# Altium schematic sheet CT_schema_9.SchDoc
size 281 x 153 mm
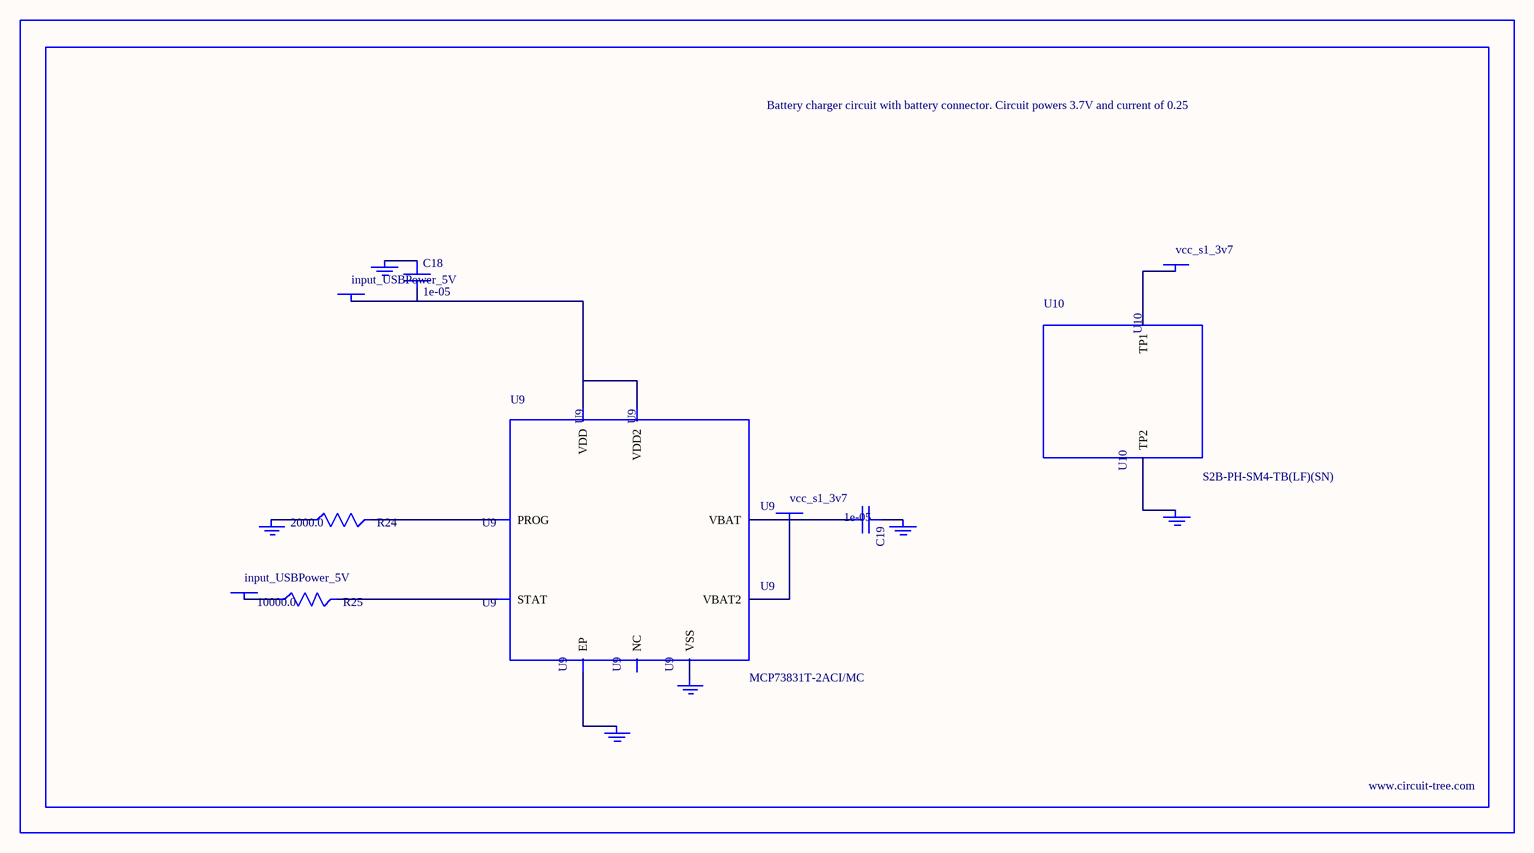
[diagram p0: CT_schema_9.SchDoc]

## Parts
BORDER8  (no value)
C18  1e-05  [C1206]
C19  1e-05  [C1206]
GND_INSTANCE_8_0  (no value)
GND_INSTANCE_8_1  (no value)
GND_INSTANCE_8_2  (no value)
GND_INSTANCE_8_3  (no value)
GND_INSTANCE_8_4  (no value)
GND_INSTANCE_8_5  (no value)
POWER_INSTANCE_8_0  input_USBPower_5V
POWER_INSTANCE_8_1  input_USBPower_5V
POWER_INSTANCE_8_2  vcc_s1_3v7
POWER_INSTANCE_8_3  vcc_s1_3v7
R24  2000.0  [R0603]
R25  10000.0  [R0603]
U9  MCP73831T-2ACI/MC  [DFN8_2X3MC]
U10  S2B-PH-SM4-TB(LF)(SN)  [JST-2-SMD]

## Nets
NetC18_1: C18.1 GND_INSTANCE_8_0.0(GND)
NetC18_2: C18.2 POWER_INSTANCE_8_0.0(PWR) U9.1(VDD) U9.2(VDD2)
NetC19_1: C19.1 GND_INSTANCE_8_1.0(GND)
NetC19_2: C19.2 POWER_INSTANCE_8_2.0(PWR) U9.3(VBAT) U9.4(VBAT2)
NetGND_INSTANCE_8_2_0: GND_INSTANCE_8_2.0(GND) R24.1
NetGND_INSTANCE_8_3_0: GND_INSTANCE_8_3.0(GND) U9.9(EP)
NetGND_INSTANCE_8_4_0: GND_INSTANCE_8_4.0(GND) U9.6(VSS)
NetGND_INSTANCE_8_5_0: GND_INSTANCE_8_5.0(GND) U10.2(TP2)
NetPOWER_INSTANCE_8_1_0: POWER_INSTANCE_8_1.0(PWR) R25.1
NetPOWER_INSTANCE_8_3_0: POWER_INSTANCE_8_3.0(PWR) U10.1(TP1)
NetR24_2: R24.2 U9.8(PROG)
NetR25_2: R25.2 U9.5(STAT)

Not connected (* = marked no-connect by the designer): U9 7(NC)

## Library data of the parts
BORDER8 = BORDER_PAGE8
C18 C19 = C1206C106K3RACTU
GND_INSTANCE_8_0-GND_INSTANCE_8_5 = GND
POWER_INSTANCE_8_0-POWER_INSTANCE_8_3 = PWR
R24 = RC0603JR-072KL
R25 = RC0603JR-0710KL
